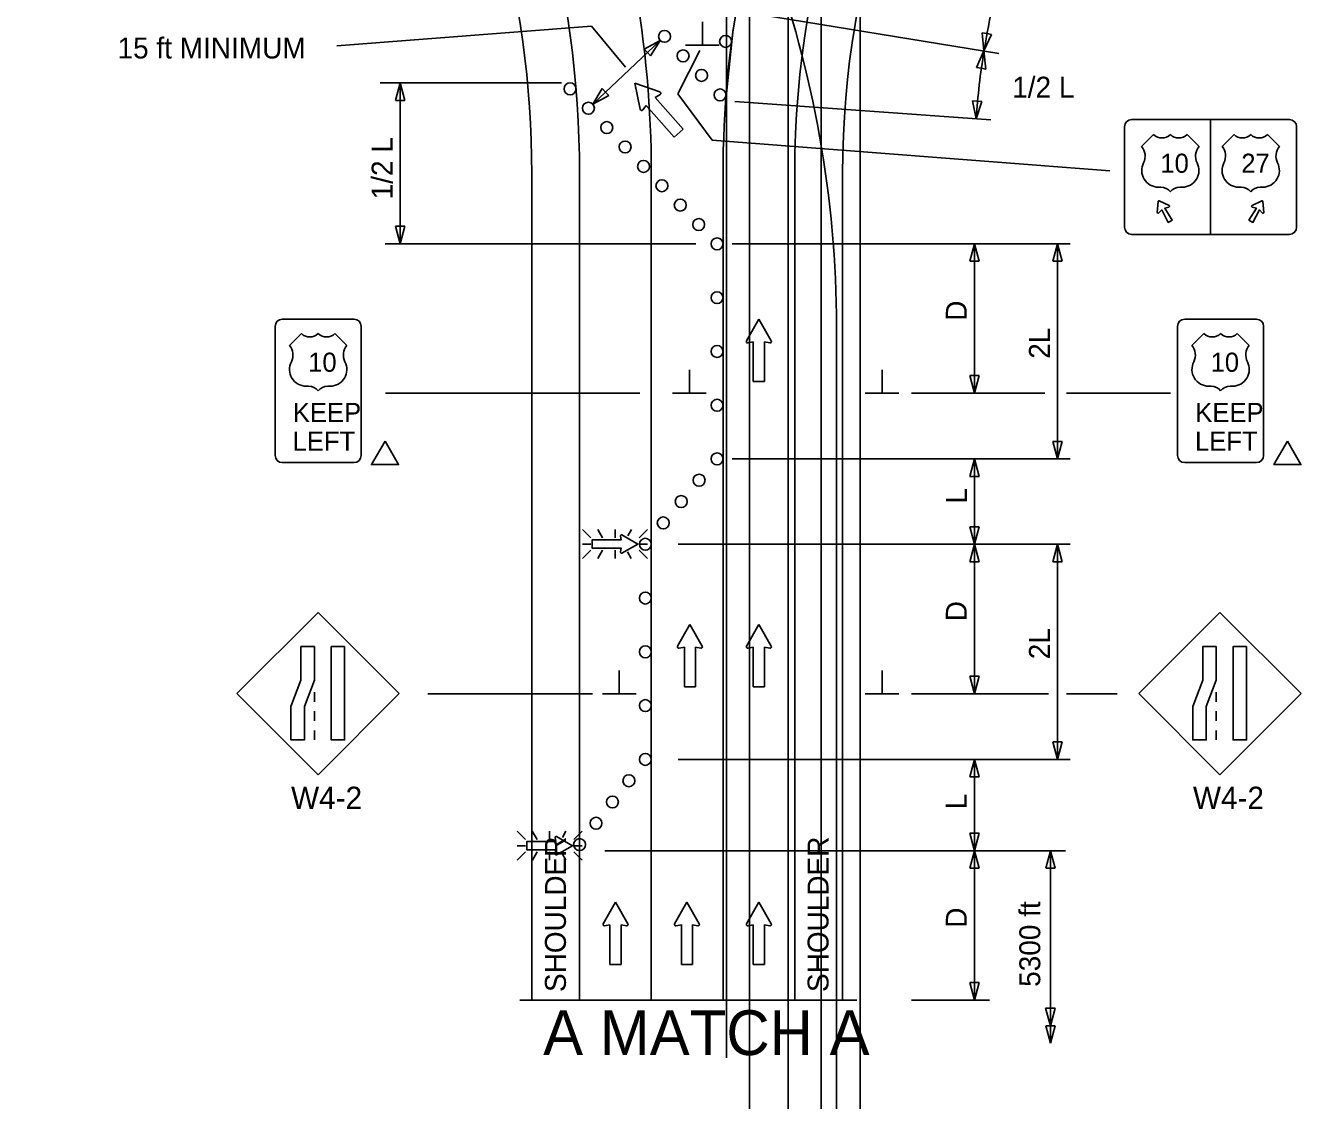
# Model space of a CAD drawing. Extents: x 16728 to 19508, y 5553 to 7079.
# Drawn here: x 16738.5 to 17166.3, y 6124.8 to 6484.5 of the extents above; entities that cross this region are included whole.
import ezdxf

# ---------------------------------------------------------------- set-up
doc = ezdxf.new("R2010")
doc.units = 0
for name, color, linetype in [('ALI_LEGAL_EX', 7, 'Continuous'), ('MT_SCRATCH_LEVEL_E', 7, 'Continuous'), ('PAVT_EDGE_EX', 7, 'Continuous'), ('TRAFFIC_SIGNS_PR', 7, 'Continuous'), ('TYPICAL_EX', 7, 'Continuous'), ('TYPICAL_TEXT_DIMEN_PR', 7, 'Continuous')]:
    doc.layers.add(name, color=color, linetype=linetype)

msp = doc.modelspace()

# ---------------------------------------------------------------- linework, layer by layer
at = {"layer": 'ALI_LEGAL_EX'}
for p, q in [((16980.68, 6974.12), (16980.68, 6155.98)), ((17004.68, 6974.12), (17004.68, 6155.98)), ((16980.68, 6877.04), (16980.68, 6013.12)), ((17004.68, 6877.04), (17004.68, 6013.12)), ((16973.01, 6139.03), (16973.01, 6639.38)), ((16993.65, 6024.8), (16993.65, 6525.15)), ((17017.65, 6024.8), (17017.65, 6525.15)), ((16947.82, 6158.38), (16947.82, 6435.06)), ((16971.82, 6158.38), (16971.82, 6435.06)), ((17009.75, 5773.57), (17009.75, 6383.76))]:
    msp.add_line(p, q, dxfattribs=at)
for points in [[(16972.59, 6458.6), (16975.21, 6483.46)], [(16947.82, 6358.38), (16947.82, 6383.38)], [(16971.82, 6358.38), (16971.82, 6383.38)], [(16947.82, 6258.38), (16947.82, 6283.38)], [(16971.82, 6258.38), (16971.82, 6283.38)], [(16947.82, 6158.38), (16947.82, 6183.38)], [(16971.82, 6158.38), (16971.82, 6183.38)]]:
    msp.add_lwpolyline(points, dxfattribs=at)
for centre, radius, start, end in [((16583.82, 6435.06), 364, 0, 40.1909), ((17311.82, 6435.06), 340, 137.516, 180), ((16645.75, 6383.76), 364, 0, 40.1909)]:
    msp.add_arc(centre, radius, start, end, dxfattribs=at)
at = {"layer": 'MT_SCRATCH_LEVEL_E'}
for p, q in [((16983.79, 6386.25), (16979.68, 6379.01)), ((16987.94, 6379.01), (16983.79, 6386.25)), ((16980.16, 6378.32), (16981.94, 6378.64)), ((16981.94, 6378.64), (16981.94, 6365.38)), ((16985.68, 6365.38), (16985.68, 6378.64)), ((16985.68, 6378.64), (16987.46, 6378.32)), ((16981.94, 6365.38), (16985.68, 6365.38)), ((16960.72, 6284.09), (16956.61, 6276.85)), ((16964.86, 6276.85), (16960.72, 6284.09)), ((16983.79, 6284.09), (16979.68, 6276.85)), ((16987.94, 6276.85), (16983.79, 6284.09)), ((16957.09, 6276.17), (16958.87, 6276.48)), ((16958.87, 6276.48), (16958.87, 6263.23)), ((16962.61, 6263.23), (16962.61, 6276.48)), ((16962.61, 6276.48), (16964.39, 6276.17)), ((16980.16, 6276.17), (16981.94, 6276.48)), ((16981.94, 6276.48), (16981.94, 6263.23)), ((16985.68, 6263.23), (16985.68, 6276.48)), ((16985.68, 6276.48), (16987.46, 6276.17)), ((16958.87, 6263.23), (16962.61, 6263.23)), ((16981.94, 6263.23), (16985.68, 6263.23)), ((16935.83, 6191.19), (16931.72, 6183.95)), ((16939.98, 6183.95), (16935.83, 6191.19)), ((16959.74, 6191.19), (16955.62, 6183.95)), ((16963.88, 6183.95), (16959.74, 6191.19)), ((16983.79, 6191.19), (16979.68, 6183.95)), ((16987.94, 6183.95), (16983.79, 6191.19)), ((16932.2, 6183.27), (16933.98, 6183.58)), ((16933.98, 6183.58), (16933.98, 6170.32)), ((16937.72, 6170.32), (16937.72, 6183.58)), ((16937.72, 6183.58), (16939.5, 6183.27)), ((16956.11, 6183.27), (16957.88, 6183.58)), ((16957.88, 6183.58), (16957.88, 6170.32)), ((16961.63, 6170.32), (16961.63, 6183.58)), ((16961.63, 6183.58), (16963.4, 6183.27)), ((16980.16, 6183.27), (16981.94, 6183.58)), ((16981.94, 6183.58), (16981.94, 6170.32)), ((16985.68, 6170.32), (16985.68, 6183.58)), ((16985.68, 6183.58), (16987.46, 6183.27)), ((16933.98, 6170.32), (16937.72, 6170.32)), ((16957.88, 6170.32), (16961.63, 6170.32)), ((16981.94, 6170.32), (16985.68, 6170.32))]:
    msp.add_line(p, q, dxfattribs=at)
for centre, start, end in [((16980.09, 6378.78), 150.4248, 279.9638), ((16987.53, 6378.78), 260.0362, 29.7731), ((16957.01, 6276.63), 150.4248, 279.9638), ((16964.46, 6276.63), 260.0362, 29.7731), ((16980.09, 6276.63), 150.4248, 279.9638), ((16987.53, 6276.63), 260.0362, 29.7731), ((16932.13, 6183.72), 150.4248, 279.9638), ((16939.57, 6183.73), 260.0362, 29.7731), ((16956.03, 6183.72), 150.4248, 279.9638), ((16963.47, 6183.73), 260.0362, 29.7731), ((16980.09, 6183.72), 150.4248, 279.9638), ((16987.53, 6183.73), 260.0362, 29.7731)]:
    msp.add_arc(centre, 0.463, start, end, dxfattribs=at)
at = {"layer": 'PAVT_EDGE_EX'}
for p, q in [((16907.82, 6435.06), (16907.82, 6158.38)), ((16923.82, 6435.06), (16923.82, 6158.38)), ((16995.82, 6435.06), (16995.82, 6158.38)), ((17011.82, 6435.06), (17011.82, 6158.38))]:
    msp.add_line(p, q, dxfattribs=at)
for centre, radius, start, end in [((17311.82, 6435.06), 316, 105.2177, 180), ((16583.82, 6435.06), 340, 0, 61.4862), ((17311.82, 6435.06), 300, 105.2177, 180), ((16583.82, 6435.06), 324, 0, 61.4862), ((17311.82, 6435.06), 300, 180, 180.00000277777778)]:
    msp.add_arc(centre, radius, start, end, dxfattribs=at)
at = {"layer": 'TRAFFIC_SIGNS_PR'}
for p, q in [((17108.51, 6453.05), (17161.31, 6453.05)), ((17134.91, 6453.05), (17134.91, 6414.65)), ((17106.11, 6450.65), (17106.11, 6417.05)), ((17163.71, 6450.65), (17163.71, 6417.05)), ((17117.09, 6422), (17117.37, 6425.62)), ((17117.74, 6425.84), (17121.02, 6424.27)), ((17152.07, 6425.84), (17148.8, 6424.27)), ((17152.73, 6422), (17152.44, 6425.62)), ((17108.51, 6414.65), (17161.31, 6414.65)), ((16821.97, 6383.86), (16821.97, 6340.66)), ((16848.37, 6386.26), (16824.37, 6386.26)), ((16850.77, 6340.66), (16850.77, 6383.86)), ((17123.87, 6383.86), (17123.87, 6340.66)), ((17150.27, 6386.26), (17126.27, 6386.26)), ((17152.67, 6340.66), (17152.67, 6383.86)), ((16824.37, 6338.26), (16848.37, 6338.26)), ((17126.27, 6338.26), (17150.27, 6338.26)), ((16927.59, 6313.05), (16924.77, 6315.87)), ((16929.89, 6315.87), (16931.52, 6313.05)), ((16935.68, 6313.05), (16935.68, 6315.87)), ((16941.15, 6315.87), (16939.94, 6313.77)), ((16946.58, 6315.86), (16943.76, 6313.05)), ((16927.59, 6311.02), (16924.77, 6311.02)), ((16943.76, 6311.02), (16946.58, 6311.02)), ((16927.59, 6308.98), (16924.77, 6306.16)), ((16931.54, 6308.98), (16929.91, 6306.16)), ((16935.68, 6308.98), (16935.68, 6306.16)), ((16939.86, 6308.35), (16941.12, 6306.16)), ((16946.58, 6306.16), (16943.76, 6308.98)), ((16836.34, 6288.11), (16809.19, 6260.96)), ((16863.49, 6260.96), (16836.34, 6288.11)), ((17138.07, 6288.11), (17110.91, 6260.96)), ((17165.22, 6260.96), (17138.07, 6288.11)), ((16809.19, 6260.96), (16836.34, 6233.81)), ((16835.09, 6261.45), (16835.09, 6258.25)), ((16836.34, 6233.81), (16863.49, 6260.96)), ((17110.91, 6260.96), (17138.07, 6233.81)), ((17136.82, 6261.45), (17136.82, 6258.25)), ((17138.07, 6233.81), (17165.22, 6260.96)), ((16835.09, 6255.05), (16835.09, 6251.85)), ((17136.82, 6255.05), (17136.82, 6251.85)), ((16835.09, 6248.65), (16835.09, 6245.45)), ((17136.82, 6248.65), (17136.82, 6245.45)), ((16905.72, 6212.1), (16902.9, 6214.92)), ((16908.01, 6214.91), (16909.64, 6212.1)), ((16913.8, 6212.1), (16913.8, 6214.91)), ((16919.27, 6214.91), (16918.06, 6212.82)), ((16924.71, 6214.91), (16921.89, 6212.1)), ((16905.72, 6210.06), (16902.9, 6210.06)), ((16905.72, 6208.03), (16902.9, 6205.21)), ((16909.67, 6208.03), (16908.04, 6205.21)), ((16913.8, 6208.03), (16913.8, 6205.21)), ((16921.89, 6210.06), (16924.71, 6210.06)), ((16924.71, 6205.21), (16921.89, 6208.03)), ((16917.99, 6207.4), (16919.25, 6205.21))]:
    msp.add_line(p, q, dxfattribs=at)
for points in [[(17120.98, 6423.79), (17119.57, 6423.4), (17122.08, 6419.42), (17120.76, 6418.65), (17118.57, 6422.82), (17117.53, 6421.79)], [(17148.83, 6423.79), (17150.24, 6423.4), (17147.73, 6419.42), (17149.06, 6418.65), (17151.25, 6422.82), (17152.29, 6421.79)], [(16937.5, 6313.7), (16937.73, 6312.4), (16928.01, 6312.4), (16928.01, 6309.66), (16937.73, 6309.66), (16937.5, 6308.35)], [(16938, 6308), (16943.31, 6311.02), (16938, 6314.06)], [(16915.63, 6212.74), (16915.86, 6211.45), (16906.14, 6211.45), (16906.14, 6208.7), (16915.86, 6208.7), (16915.63, 6207.4)], [(16916.13, 6207.05), (16921.44, 6210.06), (16916.13, 6213.1)]]:
    msp.add_lwpolyline(points, dxfattribs=at)
for points in [[(16835.09, 6276.7), (16835.09, 6265.51), (16831.75, 6256.63), (16831.75, 6245.45), (16827.26, 6245.45), (16827.26, 6256.63), (16830.6, 6265.51), (16830.6, 6276.7)], [(16845.23, 6276.7), (16845.23, 6245.45), (16840.74, 6245.45), (16840.74, 6276.7)], [(17136.82, 6276.7), (17136.82, 6265.51), (17133.47, 6256.63), (17133.47, 6245.45), (17128.98, 6245.45), (17128.98, 6256.63), (17132.32, 6265.51), (17132.32, 6276.7)], [(17146.95, 6276.7), (17146.95, 6245.45), (17142.46, 6245.45), (17142.46, 6276.7)]]:
    msp.add_lwpolyline(points, close=True, dxfattribs=at)
for centre in [(16952.24, 6480.91), (16972.68, 6479.22), (16958.43, 6474.38), (16964.62, 6467.85), (16920.63, 6463.35), (16970.82, 6461.32), (16926.78, 6456.87), (16932.93, 6450.38), (16939.07, 6443.89), (16945.22, 6437.4), (16951.37, 6430.92), (16957.52, 6424.43), (16963.67, 6417.94), (16969.82, 6411.46), (16969.82, 6411.46), (16969.82, 6393.46), (16969.82, 6375.46), (16969.82, 6357.46), (16969.82, 6339.51), (16963.82, 6332.37), (16957.82, 6325.23), (16951.82, 6318.09), (16945.82, 6310.95), (16945.82, 6292.94), (16945.82, 6274.94), (16945.82, 6256.94), (16945.82, 6238.94), (16940.32, 6231.81), (16934.82, 6224.69), (16929.32, 6217.56), (16923.83, 6210.43)]:
    msp.add_circle(centre, 2, dxfattribs=at)
for centre, radius, start, end in [((17108.51, 6450.65), 2.4, 90, 180), ((17108.51, 6450.65), 2.4, 90, 180), ((17161.31, 6450.65), 2.4, 0, 90), ((17117.35, 6421.98), 0.26, 175.5177, 314.0115), ((17117.63, 6425.6), 0.26, 64.4823, 175.5177), ((17120.91, 6424.04), 0.26, 285.9885, 64.4823), ((17148.91, 6424.04), 0.26, 115.5177, 254.0115), ((17152.19, 6425.6), 0.26, 4.4823, 115.5177), ((17152.47, 6421.98), 0.26, 225.9885, 4.4823), ((17108.51, 6417.05), 2.4, 180, 270), ((17161.31, 6417.05), 2.4, 270, 0), ((16824.37, 6383.86), 2.4, 90, 180), ((16848.37, 6383.86), 2.4, 0, 90), ((17126.27, 6383.86), 2.4, 90, 180), ((17150.27, 6383.86), 2.4, 0, 90), ((16824.37, 6340.66), 2.4, 180, 270), ((16848.37, 6340.66), 2.4, 270, 0), ((17126.27, 6340.66), 2.4, 180, 270), ((17150.27, 6340.66), 2.4, 270, 0), ((16937.84, 6313.76), 0.341, 61.4833, 189.9593), ((16937.84, 6308.3), 0.341, 170.7308, 298.8916), ((16915.97, 6212.8), 0.341, 61.4833, 189.9593), ((16915.97, 6207.35), 0.341, 170.7308, 298.8916)]:
    msp.add_arc(centre, radius, start, end, dxfattribs=at)
at = {"layer": 'TYPICAL_EX'}
for p, q in [((17111.86, 6444.05), (17115.86, 6448.05)), ((17131.06, 6444.05), (17127.06, 6448.05)), ((17138.76, 6444.05), (17142.76, 6448.05)), ((17157.96, 6444.05), (17153.96, 6448.05)), ((17117.45, 6430.44), (17118.25, 6430.44)), ((17125.46, 6430.44), (17124.66, 6430.44)), ((17144.35, 6430.44), (17145.15, 6430.44)), ((17152.36, 6430.44), (17151.56, 6430.44)), ((16826.77, 6377.46), (16830.77, 6381.46)), ((16845.97, 6377.46), (16841.97, 6381.46)), ((17128.67, 6377.46), (17132.67, 6381.46)), ((17147.87, 6377.46), (17143.87, 6381.46)), ((16832.37, 6363.85), (16833.17, 6363.85)), ((16840.38, 6363.85), (16839.58, 6363.85)), ((17134.27, 6363.85), (17135.07, 6363.85)), ((17142.28, 6363.85), (17141.48, 6363.85))]:
    msp.add_line(p, q, dxfattribs=at)
for centre, radius, start, end in [((17118.66, 6450.96), 4.04, 226.1404, 313.8596), ((17124.26, 6450.96), 4.04, 226.1404, 313.8596), ((17145.56, 6450.96), 4.04, 226.1404, 313.8596), ((17151.16, 6450.96), 4.04, 226.1404, 313.8596), ((17108.07, 6440.85), 4.96, 333.0977, 40.1936), ((17134.85, 6440.85), 4.96, 139.8064, 206.9023), ((17134.97, 6440.85), 4.96, 333.0977, 40.1936), ((17161.75, 6440.85), 4.96, 139.8064, 206.9023), ((17117.46, 6436.03), 5.59, 152.6698, 269.9013), ((17125.45, 6436.03), 5.59, 270.0987, 27.3302), ((17144.36, 6436.03), 5.59, 152.6698, 269.9013), ((17152.35, 6436.03), 5.59, 270.0987, 27.3302), ((17118.26, 6426.43), 4.01, 37.1038, 90.1385), ((17124.65, 6426.43), 4.01, 89.8615, 142.8962), ((17145.16, 6426.43), 4.01, 37.1038, 90.1385), ((17151.55, 6426.43), 4.01, 89.8615, 142.8962), ((16833.57, 6384.37), 4.04, 226.1404, 313.8596), ((16839.17, 6384.37), 4.04, 226.1404, 313.8596), ((17135.47, 6384.37), 4.04, 226.1404, 313.8596), ((17141.07, 6384.37), 4.04, 226.1404, 313.8596), ((16822.98, 6374.26), 4.96, 333.0977, 40.1936), ((16849.76, 6374.26), 4.96, 139.8064, 206.9023), ((17124.88, 6374.26), 4.96, 333.0977, 40.1936), ((17151.66, 6374.26), 4.96, 139.8064, 206.9023), ((16832.38, 6369.44), 5.59, 152.6698, 269.9013), ((16840.37, 6369.44), 5.59, 270.0987, 27.3302), ((17134.28, 6369.44), 5.59, 152.6698, 269.9013), ((17142.27, 6369.44), 5.59, 270.0987, 27.3302), ((16833.18, 6359.84), 4.01, 37.1038, 90.1385), ((16839.57, 6359.84), 4.01, 89.8615, 142.8962), ((17135.08, 6359.84), 4.01, 37.1038, 90.1385), ((17141.47, 6359.84), 4.01, 89.8615, 142.8962)]:
    msp.add_arc(centre, radius, start, end, dxfattribs=at)
at = {"layer": 'TYPICAL_TEXT_DIMEN_PR'}
for p, q in [((17064.05, 6475.22), (16979.21, 6488.97)), ((16927.8, 6484.32), (16842.59, 6477.76)), ((16939.16, 6470.62), (16927.8, 6484.32)), ((16964.92, 6477.95), (16964.92, 6485.73)), ((17059.11, 6476.02), (17058.5, 6482.06)), ((17058.5, 6482.06), (17060.05, 6481.81)), ((17059.11, 6476.02), (17058.5, 6482.06)), ((17058.5, 6482.06), (17060.05, 6481.81)), ((17060.05, 6481.81), (17061.6, 6481.55)), ((17060.05, 6481.81), (17061.6, 6481.55)), ((16950.78, 6479.54), (16928.23, 6458.24)), ((16945.44, 6476.66), (16950.78, 6479.54)), ((16950.78, 6479.54), (16947.6, 6474.37)), ((16970.55, 6477.95), (16959.3, 6477.95)), ((17061.6, 6481.55), (17059.11, 6476.02)), ((17061.6, 6481.55), (17059.11, 6476.02)), ((16946.52, 6475.52), (16945.44, 6476.66)), ((16947.6, 6474.37), (16946.52, 6475.52)), ((16964.04, 6476.17), (16956.66, 6461.67)), ((17056.63, 6470.48), (17059.11, 6476.02)), ((17059.11, 6476.02), (17059.73, 6469.98)), ((17058.18, 6470.23), (17056.63, 6470.48)), ((17059.73, 6469.98), (17058.18, 6470.23)), ((16857.14, 6465.35), (16917.72, 6465.35)), ((16862.25, 6459.49), (16863.82, 6465.35)), ((16863.82, 6465.35), (16863.82, 6411.51)), ((16863.82, 6465.35), (16865.39, 6459.49)), ((16950.7, 6462.31), (16942.28, 6465.2)), ((16942.28, 6465.2), (16944.08, 6456.51)), ((16928.23, 6458.24), (16931.41, 6463.41)), ((16933.57, 6461.12), (16928.23, 6458.24)), ((16931.41, 6463.41), (16932.49, 6462.26)), ((16932.49, 6462.26), (16933.57, 6461.12)), ((16949.15, 6460.43), (16950.8, 6461.43)), ((16958.47, 6449.8), (16949.15, 6460.43)), ((16956.66, 6461.67), (16968.23, 6446.16)), ((16863.82, 6459.49), (16862.25, 6459.49)), ((16865.39, 6459.49), (16863.82, 6459.49)), ((16944.95, 6456.3), (16946.15, 6457.8)), ((16946.15, 6457.8), (16955.47, 6447.16)), ((17061.46, 6452.97), (16975.72, 6459.1)), ((17056.47, 6453.32), (17055.32, 6459.28)), ((17055.32, 6459.28), (17056.89, 6459.17)), ((17058.45, 6459.06), (17056.47, 6453.32)), ((17056.89, 6459.17), (17058.45, 6459.06)), ((16955.47, 6447.16), (16958.47, 6449.8)), ((16968.23, 6446.16), (17101.17, 6435.93)), ((16863.82, 6411.51), (16862.25, 6417.37)), ((16862.25, 6417.37), (16863.82, 6417.37)), ((16863.82, 6417.37), (16865.39, 6417.37)), ((16865.39, 6417.37), (16863.82, 6411.51)), ((16962.71, 6411.51), (16858.82, 6411.51)), ((17087.96, 6411.51), (16974.86, 6411.51)), ((17054.34, 6405.65), (17055.91, 6411.51)), ((17055.91, 6411.51), (17057.48, 6405.65)), ((17055.91, 6411.51), (17055.91, 6361.51)), ((17082.15, 6405.65), (17083.72, 6411.51)), ((17083.72, 6411.51), (17083.72, 6339.51)), ((17083.72, 6411.51), (17085.29, 6405.65)), ((17055.91, 6405.65), (17054.34, 6405.65)), ((17057.48, 6405.65), (17055.91, 6405.65)), ((17083.72, 6405.65), (17082.15, 6405.65)), ((17085.29, 6405.65), (17083.72, 6405.65)), ((16960.57, 6361.51), (16960.57, 6369.29)), ((17025.04, 6361.51), (17025.04, 6369.29)), ((17055.91, 6361.51), (17054.34, 6367.37)), ((17054.34, 6367.37), (17055.91, 6367.37)), ((17055.91, 6367.37), (17057.48, 6367.37)), ((17057.48, 6367.37), (17055.91, 6361.51)), ((16858.91, 6361.51), (16944.03, 6361.51)), ((16966.19, 6361.51), (16954.94, 6361.51)), ((17030.66, 6361.51), (17019.41, 6361.51)), ((17079.49, 6361.51), (17034.91, 6361.51)), ((17121.56, 6361.51), (17086.72, 6361.51)), ((17083.72, 6339.51), (17082.15, 6345.37)), ((17082.15, 6345.37), (17083.72, 6345.37)), ((17083.72, 6345.37), (17085.29, 6345.37)), ((17085.29, 6345.37), (17083.72, 6339.51)), ((16974.86, 6339.51), (17087.96, 6339.51)), ((17054.34, 6333.65), (17055.91, 6339.51)), ((17055.91, 6310.94), (17055.91, 6339.51)), ((17055.91, 6339.51), (17057.48, 6333.65)), ((17055.91, 6333.65), (17054.34, 6333.65)), ((17057.48, 6333.65), (17055.91, 6333.65)), ((17055.91, 6310.94), (17054.34, 6316.81)), ((17054.34, 6316.81), (17055.91, 6316.81)), ((17055.91, 6316.81), (17057.48, 6316.81)), ((17057.48, 6316.81), (17055.91, 6310.94)), ((17087.96, 6310.94), (16956.81, 6310.94)), ((17054.34, 6305.08), (17055.91, 6310.94)), ((17055.91, 6310.94), (17055.91, 6260.94)), ((17055.91, 6310.94), (17057.48, 6305.08)), ((17082.15, 6305.08), (17083.72, 6310.94)), ((17083.72, 6310.94), (17085.29, 6305.08)), ((17083.72, 6310.94), (17083.72, 6238.94)), ((17055.91, 6305.08), (17054.34, 6305.08)), ((17057.48, 6305.08), (17055.91, 6305.08)), ((17083.72, 6305.08), (17082.15, 6305.08)), ((17085.29, 6305.08), (17083.72, 6305.08)), ((16937.1, 6260.94), (16937.1, 6268.73)), ((17025.04, 6260.94), (17025.04, 6268.73)), ((17055.91, 6260.94), (17054.34, 6266.81)), ((17054.34, 6266.81), (17055.91, 6266.81)), ((17055.91, 6266.81), (17057.48, 6266.81)), ((17057.48, 6266.81), (17055.91, 6260.94)), ((16873.02, 6260.94), (16928.11, 6260.94)), ((16942.73, 6260.94), (16931.48, 6260.94)), ((17030.66, 6260.94), (17019.41, 6260.94)), ((17080.65, 6260.94), (17034.91, 6260.94)), ((17103.64, 6260.94), (17086.72, 6260.94)), ((17083.72, 6238.94), (17082.15, 6244.81)), ((17082.15, 6244.81), (17083.72, 6244.81)), ((17083.72, 6244.81), (17085.29, 6244.81)), ((17085.29, 6244.81), (17083.72, 6238.94)), ((16956.81, 6238.94), (17087.96, 6238.94)), ((17054.34, 6233.08), (17055.91, 6238.94)), ((17055.91, 6208.38), (17055.91, 6238.94)), ((17055.91, 6238.94), (17057.48, 6233.08)), ((17055.91, 6233.08), (17054.34, 6233.08)), ((17057.48, 6233.08), (17055.91, 6233.08)), ((17055.91, 6208.38), (17054.34, 6214.24)), ((17054.34, 6214.24), (17055.91, 6214.24)), ((17055.91, 6214.24), (17057.48, 6214.24)), ((17057.48, 6214.24), (17055.91, 6208.38)), ((16932.31, 6208.38), (17086.35, 6208.38)), ((16933.08, 6208.38), (17060.91, 6208.38)), ((17054.34, 6202.52), (17055.91, 6208.38)), ((17055.91, 6208.38), (17055.91, 6158.38)), ((17055.91, 6208.38), (17057.48, 6202.52)), ((17079.78, 6202.52), (17081.35, 6208.38)), ((17081.35, 6208.38), (17081.35, 6143.96)), ((17081.35, 6208.38), (17082.92, 6202.52)), ((17055.91, 6202.52), (17054.34, 6202.52)), ((17057.48, 6202.52), (17055.91, 6202.52)), ((17081.35, 6202.52), (17079.78, 6202.52)), ((17082.92, 6202.52), (17081.35, 6202.52)), ((17055.91, 6158.38), (17054.34, 6164.24)), ((17054.34, 6164.24), (17055.91, 6164.24)), ((17055.91, 6164.24), (17057.48, 6164.24)), ((17057.48, 6164.24), (17055.91, 6158.38)), ((16903.89, 6158.38), (17016.54, 6158.38)), ((17060.91, 6158.38), (17034.91, 6158.38)), ((17081.32, 6149.82), (17079.75, 6155.68)), ((17079.75, 6155.68), (17081.32, 6155.68)), ((17081.32, 6155.68), (17082.89, 6155.68)), ((17082.89, 6155.68), (17081.32, 6149.82)), ((17081.35, 6143.96), (17079.78, 6149.83)), ((17079.78, 6149.83), (17081.35, 6149.83)), ((17081.35, 6149.83), (17082.92, 6149.83)), ((17082.92, 6149.83), (17081.35, 6143.96))]:
    msp.add_line(p, q, dxfattribs=at)
for points in [[(16858.74, 6345.44), (16854.21, 6337.6), (16863.26, 6337.6)], [(17160.64, 6345.44), (17156.12, 6337.6), (17165.17, 6337.6)]]:
    msp.add_lwpolyline(points, close=True, dxfattribs=at)
for centre, radius, start, end in [((17311.82, 6435.06), 256, 167.0592, 170.7929), ((17311.82, 6435.06), 256, 170.7929, 175.9084), ((16950.53, 6461.84), 0.494, 301.2737, 71.0106), ((16944.56, 6456.61), 0.494, 191.6624, 321.2013)]:
    msp.add_arc(centre, radius, start, end, dxfattribs=at)

# ---------------------------------------------------------------- texts
at = {"layer": 'TRAFFIC_SIGNS_PR'}
for s, height, p in [('10', 6.4, (17118.12, 6435.25)), ('27', 6.4, (17145.19, 6435.25)), ('10', 6.4, (16833.03, 6368.66)), ('10', 6.4, (17134.93, 6368.66)), ('KEEP', 6.4, (16827.91, 6351.86)), ('KEEP', 6.4, (17129.81, 6351.86)), ('LEFT', 6.4, (16827.82, 6342.26)), ('LEFT', 6.4, (17129.72, 6342.26)), ('W4-2', 7.44, (16827.3, 6222.37)), ('W4-2', 7.44, (17129.02, 6222.37))]:
    msp.add_text(s, height=height, dxfattribs=at).set_placement(p)
at = {"layer": 'TYPICAL_TEXT_DIMEN_PR'}
for s, height, p in [('15 ft MINIMUM', 7, (16769.25, 6473.51)), ('1/2 L', 7, (17068.56, 6460.4)), ('A MATCH A', 15, (16911.63, 6139.98))]:
    msp.add_text(s, height=height, dxfattribs=at).set_placement(p)
for s, p in [('1/2 L', (16861.26, 6426.37)), ('D', (17053.35, 6385.73)), ('2L', (17081.16, 6373.01)), ('L', (17053.45, 6324.58)), ('D', (17053.35, 6285.16)), ('2L', (17081.16, 6272.45)), ('L', (17053.35, 6222.24)), ('SHOULDER', (16919.25, 6161.09)), ('SHOULDER', (17007.11, 6161.09)), ('5300 ft', (17077.94, 6162.83)), ('D', (17053.35, 6182.6))]:
    msp.add_text(s, height=7, rotation=90, dxfattribs=at).set_placement(p)

doc.saveas('drawing.dxf')
